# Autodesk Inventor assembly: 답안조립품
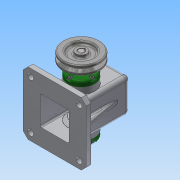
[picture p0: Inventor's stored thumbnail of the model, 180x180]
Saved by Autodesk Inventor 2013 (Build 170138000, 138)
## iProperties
Created: 2016-02
Part Number: 답안조립품
Document SubType Name: Assembly
Designer: Administrator
Author: Administrator
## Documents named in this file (16)
- C:\Users\Administrator\Desktop\460212V1017\답안조립품.iam
- C:\Users\Administrator\Desktop\460212V1017\본체.ipt
- C:\Users\Administrator\Desktop\460212V1017\뒤커버.ipt
- C:\Users\Administrator\Desktop\460212V1017\링크.ipt
- C:\Users\Administrator\Desktop\460212V1017\베어링 12 x 32 x 10.ipt
- C:\Users\Administrator\Desktop\460212V1017\앞커버.ipt
- C:\Users\Administrator\Desktop\460212V1017\오일실 12 25 7.ipt
- C:\Users\Administrator\Desktop\460212V1017\편심축.ipt
- C:\Users\Administrator\Desktop\460212V1017\키 4 x 4 x 10.ipt
- C:\Users\Administrator\Desktop\460212V1017\V벨트풀리.ipt
- C:\Users\Administrator\Desktop\460212V1017\멈춤나사 M3x8.ipt
- C:\Users\Administrator\Desktop\460212V1017\부시.ipt
- C:\Users\Administrator\Desktop\460212V1017\슬라이드.ipt
- C:\Users\Administrator\Desktop\460212V1017\고정핀 1.2 x 10.ipt
- C:\Users\Administrator\Desktop\460212V1017\핀 5 x 18.ipt
- C:\Users\Administrator\Desktop\460212V1017\볼트 M4 x 12.ipt
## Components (11 placed, 4 different names)
1. V벨트풀리:1
2. 고정핀 1.2 x 10:1 — 플러쉬:1
3. 핀 5 x 18:1 — 각도:1, 각도:2
4. ISO 4762 M4 x 12:1
5. ISO 4762 M4 x 12:3
6. ISO 4762 M4 x 12:4
7. ISO 4762 M4 x 12:5
8. ISO 4762 M4 x 12:2
9. ISO 4762 M4 x 12:6
10. ISO 4762 M4 x 12:7
11. ISO 4762 M4 x 12:8
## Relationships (3: Angle 2, Flush 1)
- 플러쉬:1 [Flush]: 고정핀 1.2 x 10:1
- 각도:1 [Angle]: 핀 5 x 18:1
- 각도:2 [Angle]: 핀 5 x 18:1
